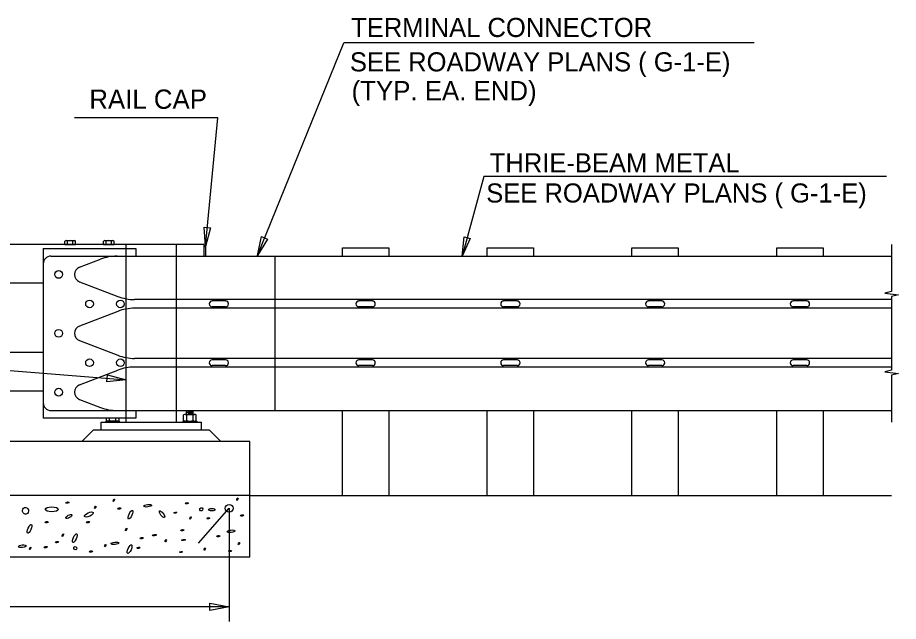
# Model space of a CAD drawing. Extents: x 0 to 45.3, y 0 to 31.4.
# Drawn here: x 13.86 to 23.37, y 13.57 to 20.09 of the extents above; entities that cross this region are included whole.
import ezdxf

# ---------------------------------------------------------------- set-up
doc = ezdxf.new("R2010")
doc.units = 0
for name, color, linetype in [('BRDG_ANNO_General-Notes', 7, 'Continuous'), ('BRDG_BASE_Hidden-Line', 7, 'Continuous'), ('BRDG_BASE_Obj-Line', 7, 'Continuous'), ('BRDG_BASE_Pattern', 7, 'Continuous'), ('BRDG_BASE_Rebar', 7, 'Continuous'), ('Default', 7, 'Continuous')]:
    doc.layers.add(name, color=color, linetype=linetype)

# ---------------------------------------------------------------- blocks, each defined once
blk = doc.blocks.new('TERM')
at = {"layer": 'Default'}
for p, q in [((-1.6, -0.267), (-1.6, 0.267)), ((-1.6, 0.267), (0, 0)), ((0, 0), (-1.6, -0.267))]:
    blk.add_line(p, q, dxfattribs=at)

msp = doc.modelspace()

# ---------------------------------------------------------------- linework, layer by layer
at = {"layer": 'BRDG_ANNO_General-Notes'}
for p, q in [((16.4516, 17.5248), (17.3838, 19.8198)), ((21.8149, 19.8198), (17.3838, 19.8198)), ((16.0251, 19.0123), (14.4785, 19.0123)), ((15.8907, 17.6226), (16.0251, 19.0123)), ((18.8974, 18.3786), (18.6603, 17.5184)), ((23.242, 18.3786), (18.8974, 18.3786)), ((15.8763, 17.8316), (15.9449, 17.825)), ((15.8907, 17.6226), (15.8763, 17.8316)), ((15.9449, 17.825), (15.8907, 17.6226)), ((16.4516, 17.5248), (16.4975, 17.7292)), ((16.5613, 17.7033), (16.4516, 17.5248)), ((16.4975, 17.7292), (16.5613, 17.7033)), ((18.6603, 17.5184), (18.682, 17.7268)), ((18.7484, 17.7085), (18.6603, 17.5184)), ((18.682, 17.7268), (18.7484, 17.7085)), ((6.9457, 16.8451), (15.0365, 16.1813)), ((14.8274, 16.1596), (14.8337, 16.2368)), ((15.0365, 16.1813), (14.8274, 16.1596)), ((14.8337, 16.2368), (15.0365, 16.1813)), ((16.1476, 14.7962), (16.1476, 13.5749)), ((16.1476, 13.7312), (11.1476, 13.7312))]:
    msp.add_line(p, q, dxfattribs=at)
at = {"layer": 'BRDG_BASE_Hidden-Line'}
for p, q in [((15.0365, 15.7684), (15.0365, 17.6434)), ((15.5782, 15.8518), (15.5782, 17.6434))]:
    msp.add_line(p, q, dxfattribs=at)
at = {"layer": 'BRDG_BASE_Obj-Line'}
for p, q in [((14.3738, 17.6434), (14.3738, 17.6818)), ((14.3881, 17.6864), (14.4324, 17.6864)), ((14.4031, 17.6434), (14.4031, 17.6818)), ((14.4324, 17.6864), (14.4767, 17.6864)), ((14.4617, 17.6434), (14.4617, 17.6818)), ((14.4909, 17.6434), (14.4909, 17.6818)), ((14.7905, 17.6434), (14.7905, 17.6818)), ((14.8047, 17.6864), (14.849, 17.6864)), ((14.8197, 17.6434), (14.8197, 17.6818)), ((14.849, 17.6864), (14.8933, 17.6864)), ((14.8783, 17.6434), (14.8783, 17.6818)), ((14.9076, 17.6434), (14.9076, 17.6818)), ((15.8751, 17.6434), (3.8074, 17.6434)), ((14.1407, 17.6018), (14.1407, 15.7684)), ((14.1407, 17.6018), (15.1407, 17.6018)), ((14.3738, 17.6434), (14.4324, 17.6434)), ((14.4324, 17.6434), (14.4909, 17.6434)), ((14.7905, 17.6434), (14.849, 17.6434)), ((14.849, 17.6434), (14.9076, 17.6434)), ((15.1407, 17.6018), (15.1407, 17.5184)), ((15.8751, 17.6434), (15.8751, 17.5184)), ((15.8751, 17.6226), (15.8907, 17.6226)), ((15.8907, 17.6226), (15.8907, 17.5184)), ((17.3699, 17.607), (17.8699, 17.607)), ((17.3699, 17.5184), (17.3699, 17.607)), ((17.8699, 17.607), (17.8699, 17.5184)), ((18.9324, 17.607), (19.4324, 17.607)), ((18.9324, 17.5184), (18.9324, 17.607)), ((19.4324, 17.607), (19.4324, 17.5184)), ((20.4949, 17.607), (20.9949, 17.607)), ((20.4949, 17.5184), (20.4949, 17.607)), ((20.9949, 17.607), (20.9949, 17.5184)), ((22.0574, 17.607), (22.5574, 17.607)), ((22.0574, 17.5184), (22.0574, 17.607)), ((22.5574, 17.607), (22.5574, 17.5184)), ((14.224, 17.5184), (16.6407, 17.5184)), ((16.6407, 17.5184), (23.2959, 17.5184)), ((16.6407, 17.5184), (16.6407, 15.8518)), ((14.1407, 17.4351), (14.1407, 15.9351)), ((14.5329, 17.3982), (14.7573, 17.4849)), ((14.1407, 17.2268), (3.8074, 17.2268)), ((14.5329, 17.2428), (14.9461, 17.0832)), ((16.6407, 17.0497), (15.1262, 17.0497)), ((23.2959, 17.0497), (16.6407, 17.0497)), ((14.9462, 16.9224), (14.5329, 16.7628)), ((16.6407, 16.9559), (15.1262, 16.9559)), ((23.2959, 16.9559), (16.6407, 16.9559)), ((14.5329, 16.6074), (14.9461, 16.4478)), ((14.1407, 16.4768), (3.8074, 16.4768)), ((16.6407, 16.4143), (15.1262, 16.4143)), ((23.2959, 16.4143), (16.6407, 16.4143)), ((14.5329, 16.1274), (14.9461, 16.287)), ((16.6407, 16.3205), (15.1262, 16.3205)), ((23.2959, 16.3205), (16.6407, 16.3205)), ((14.1407, 16.0601), (3.8074, 16.0601)), ((14.5329, 15.972), (14.7573, 15.8853)), ((14.224, 15.8518), (16.6407, 15.8518)), ((15.1407, 15.8518), (15.1407, 15.7684)), ((15.5782, 15.7268), (15.5782, 15.8518)), ((15.6557, 15.7426), (15.6557, 15.8047)), ((15.6732, 15.8101), (15.724, 15.8101)), ((15.6876, 15.8101), (15.6876, 15.8518)), ((15.6876, 15.8344), (15.7605, 15.8344)), ((15.6898, 15.7426), (15.6898, 15.8047)), ((15.6997, 15.8466), (15.7484, 15.8466)), ((15.6997, 15.8223), (15.7484, 15.8223)), ((15.724, 15.8101), (15.7749, 15.8101)), ((15.7582, 15.7426), (15.7582, 15.8047)), ((15.7605, 15.8101), (15.7605, 15.8518)), ((15.7924, 15.7426), (15.7924, 15.8047)), ((16.6407, 15.8518), (23.2959, 15.8518)), ((17.3699, 14.9351), (17.3699, 15.8518)), ((17.8699, 15.8518), (17.8699, 14.9351)), ((18.9324, 14.9351), (18.9324, 15.8518)), ((19.4324, 15.8518), (19.4324, 14.9351)), ((20.4949, 14.9351), (20.4949, 15.8518)), ((20.9949, 15.8518), (20.9949, 14.9351)), ((22.0574, 14.9351), (22.0574, 15.8518)), ((22.5574, 15.8518), (22.5574, 14.9351)), ((15.1407, 15.7684), (14.1407, 15.7684)), ((14.7657, 15.7268), (15.849, 15.7268)), ((14.7657, 15.6434), (14.7657, 15.7268)), ((14.8224, 15.7426), (14.8224, 15.7684)), ((14.8907, 15.7372), (14.8399, 15.7372)), ((14.8565, 15.7426), (14.8565, 15.7684)), ((14.9415, 15.7372), (14.8907, 15.7372)), ((14.9249, 15.7426), (14.9249, 15.7684)), ((14.959, 15.7426), (14.959, 15.7684)), ((15.0365, 15.7268), (15.0365, 15.7684)), ((15.6732, 15.7372), (15.724, 15.7372)), ((15.724, 15.7372), (15.7749, 15.7372)), ((15.849, 15.6434), (15.849, 15.7268)), ((14.5573, 15.5184), (14.6823, 15.6434)), ((14.6823, 15.6434), (15.9324, 15.6434)), ((16.0574, 15.5184), (15.9324, 15.6434)), ((16.3699, 15.5184), (2.6751, 15.5184)), ((16.3699, 14.9351), (16.3699, 15.5184)), ((16.3699, 14.9351), (2.6751, 14.9351)), ((16.3699, 14.9351), (23.2959, 14.9351)), ((16.3699, 14.2684), (16.3699, 14.9351)), ((16.3699, 14.2684), (2.6751, 14.2684))]:
    msp.add_line(p, q, dxfattribs=at)
msp.add_lwpolyline([(23.2959, 17.6447), (23.2959, 17.1372), (23.2221, 17.1188), (23.3698, 17.1003), (23.2959, 17.0819), (23.2959, 16.6851), (23.2959, 16.2883), (23.2221, 16.2699), (23.3698, 16.2514), (23.2959, 16.233), (23.2959, 15.7255)], dxfattribs=at)
for points in [[(14.9636, 15.7268), (14.9636, 15.7372), (14.8178, 15.7372), (14.8178, 15.7268)], [(15.6511, 15.7268), (15.6511, 15.7372), (15.7969, 15.7372), (15.7969, 15.7268)]]:
    msp.add_lwpolyline(points, close=True, dxfattribs=at)
for centre, radius, start, end in [((14.3884, 17.661), 0.0254, 54.7697, 125.2303), ((14.4324, 17.5918), 0.0946, 71.96845, 108.03155), ((14.4763, 17.661), 0.0254, 54.7697, 125.2303), ((14.8051, 17.661), 0.0254, 54.7697, 125.2303), ((14.849, 17.5918), 0.0946, 71.96845, 108.03155), ((14.893, 17.661), 0.0254, 54.7697, 125.2303), ((14.224, 17.4351), 0.0833, 90, 180), ((14.9374, 17.0184), 0.5, 90, 111.10753), ((14.563, 17.3205), 0.0833, 111.11599, 248.88034), ((15.1262, 17.5497), 0.5, 248.89319, 270), ((15.1262, 16.4559), 0.5, 90, 111.09879), ((14.563, 16.6851), 0.0833, 111.11998, 248.88366), ((15.1262, 16.9143), 0.5, 248.88039, 270), ((15.1262, 15.8205), 0.5, 90, 111.10681), ((14.563, 16.0497), 0.0833, 111.11966, 248.88401), ((14.224, 15.9351), 0.0833, 180, 270), ((14.9374, 16.3518), 0.5, 248.89247, 270), ((15.6728, 15.7805), 0.0296, 54.7697, 125.2303), ((15.724, 15.6997), 0.1104, 71.96845, 108.03155), ((15.7753, 15.7805), 0.0296, 54.7697, 125.2303), ((14.8394, 15.7668), 0.0296, 234.7697, 305.2303), ((14.8907, 15.8476), 0.1104, 251.96845, 288.03155), ((14.942, 15.7668), 0.0296, 234.7697, 305.2303), ((15.6728, 15.7668), 0.0296, 234.7697, 305.2303), ((15.724, 15.8476), 0.1104, 251.96845, 288.03155), ((15.7753, 15.7668), 0.0296, 234.7697, 305.2303)]:
    msp.add_arc(centre, radius, start, end, dxfattribs=at)
at = {"layer": 'BRDG_BASE_Pattern'}
for centre, major_axis, ratio in [((14.4029, 14.8571), (-0.0164, -0.0024), 0.420578), ((14.9035, 14.8823), (0.0059, 0.0129), 0.353486), ((15.2681, 14.8241), (-0.0423, -0.0047), 0.315594), ((15.6923, 14.8501), (-0.0164, -0.0024), 0.420578), ((16.2362, 14.8944), (0.0059, 0.0129), 0.353486), ((13.9488, 14.7694), (-0.0094, 0.0352), 0.905037), ((14.233, 14.7847), (0.0705, 0), 0.363671), ((14.4181, 14.708), (0.0329, 0.0188), 0.385178), ((14.6342, 14.7291), (0.047, 0.0211), 0.389672), ((14.7023, 14.8066), (0.0059, 0.0129), 0.353486), ((14.9618, 14.7937), (-0.0164, -0.0024), 0.420578), ((15.0828, 14.7268), (0.0211, 0.047), 0.317581), ((15.4229, 14.7317), (0.0258, -0.0352), 0.360274), ((15.5681, 14.7485), (-0.0164, -0.0024), 0.420578), ((15.8467, 14.785), (-0.0047, 0.0176), 0.905037), ((15.9594, 14.7816), (0.0352, 0), 0.363671), ((14.1783, 14.6453), (-0.0164, -0.0024), 0.420578), ((14.6233, 14.6463), (-0.0164, -0.0024), 0.420578), ((15.731, 14.6915), (0.0059, 0.0129), 0.353486), ((15.9225, 14.688), (-0.0164, -0.0024), 0.420578), ((16.286, 14.7192), (-0.0164, -0.0024), 0.420578), ((13.9934, 14.5744), (0.0211, 0.047), 0.317581), ((15.0361, 14.5669), (0.0059, 0.0129), 0.353486), ((15.6435, 14.559), (-0.0164, -0.0024), 0.420578), ((16.1684, 14.5483), (-0.0423, -0.0047), 0.315594), ((14.3523, 14.506), (0.0059, 0.0129), 0.353486), ((14.4815, 14.4731), (0.0211, 0.047), 0.317581), ((15.2025, 14.4742), (-0.0164, -0.0024), 0.420578), ((15.3408, 14.5055), (-0.0211, -0.0024), 0.315594), ((15.4632, 14.4461), (0.0059, 0.0129), 0.353486), ((15.6535, 14.4536), (-0.0211, -0.0024), 0.315594), ((16.0314, 14.494), (-0.0164, -0.0024), 0.420578), ((13.9159, 14.3865), (-0.0423, -0.0047), 0.315594), ((14.0005, 14.3631), (0.0059, 0.0129), 0.353486), ((14.1673, 14.3761), (-0.0164, -0.0024), 0.420578), ((14.2885, 14.4311), (-0.0164, -0.0024), 0.420578), ((14.4863, 14.3656), (-0.0047, 0.0176), 0.905037), ((14.8103, 14.3932), (0.0059, 0.0129), 0.353486), ((14.9147, 14.4179), (-0.0423, -0.0047), 0.315594), ((15.0734, 14.3557), (0.0211, 0.047), 0.317581), ((15.1685, 14.37), (-0.0164, -0.0024), 0.420578), ((15.8837, 14.3557), (0.0059, 0.0129), 0.353486), ((16.2532, 14.4146), (0.0059, 0.0129), 0.353486), ((14.6565, 14.3286), (-0.0164, -0.0024), 0.420578), ((15.6289, 14.3239), (-0.0164, -0.0024), 0.420578), ((16.1552, 14.3344), (-0.0164, -0.0024), 0.420578)]:
    msp.add_ellipse(centre, major_axis=major_axis, ratio=ratio, dxfattribs=at)
at = {"layer": 'BRDG_BASE_Rebar'}
for p, q in [((16.1094, 17.0341), (15.9636, 17.0341)), ((17.6928, 17.0341), (17.5469, 17.0341)), ((19.2553, 17.0341), (19.1094, 17.0341)), ((20.8178, 17.0341), (20.6719, 17.0341)), ((22.3803, 17.0341), (22.2344, 17.0341)), ((16.1094, 16.9716), (15.9636, 16.9716)), ((17.6928, 16.9716), (17.5469, 16.9716)), ((19.2553, 16.9716), (19.1094, 16.9716)), ((20.8178, 16.9716), (20.6719, 16.9716)), ((22.3803, 16.9716), (22.2344, 16.9716)), ((16.1094, 16.3986), (15.9636, 16.3986)), ((17.6928, 16.3986), (17.5469, 16.3986)), ((19.2553, 16.3986), (19.1094, 16.3986)), ((20.8178, 16.3986), (20.6719, 16.3986)), ((22.3803, 16.3986), (22.2344, 16.3986)), ((16.1094, 16.3361), (15.9636, 16.3361)), ((17.6928, 16.3361), (17.5469, 16.3361)), ((19.2553, 16.3361), (19.1094, 16.3361)), ((20.8178, 16.3361), (20.6719, 16.3361)), ((22.3803, 16.3361), (22.2344, 16.3361)), ((15.8169, 14.4212), (16.1476, 14.7962))]:
    msp.add_line(p, q, dxfattribs=at)
for centre in [(14.3074, 17.3205), (14.6407, 17.0028), (14.974, 17.0028), (14.3074, 16.6851), (14.6407, 16.3674), (14.974, 16.3674), (14.3074, 16.0497), (16.1476, 14.7962)]:
    msp.add_circle(centre, 0.0417, dxfattribs=at)
for centre, start, end in [((15.9636, 17.0028), 90, 270), ((16.1094, 17.0028), 270, 90), ((17.5469, 17.0028), 90, 270), ((17.6928, 17.0028), 270, 90), ((19.1094, 17.0028), 90, 270), ((19.2553, 17.0028), 270, 90), ((20.6719, 17.0028), 90, 270), ((20.8178, 17.0028), 270, 90), ((22.2344, 17.0028), 90, 270), ((22.3803, 17.0028), 270, 90), ((15.9636, 16.3674), 90, 270), ((16.1094, 16.3674), 270, 90), ((17.5469, 16.3674), 90, 270), ((17.6928, 16.3674), 270, 90), ((19.1094, 16.3674), 90, 270), ((19.2553, 16.3674), 270, 90), ((20.6719, 16.3674), 90, 270), ((20.8178, 16.3674), 270, 90), ((22.2344, 16.3674), 90, 270), ((22.3803, 16.3674), 270, 90)]:
    msp.add_arc(centre, 0.0312, start, end, dxfattribs=at)

# ---------------------------------------------------------------- block references
at = {"layer": 'BRDG_ANNO_General-Notes', "xscale": 0.13020833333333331, "yscale": 0.146484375}
msp.add_blockref('TERM', (16.1476, 13.7312), dxfattribs=at)

# ---------------------------------------------------------------- texts
at = {"layer": 'BRDG_ANNO_General-Notes'}
for s, height, p in [('TERMINAL CONNECTOR', 0.20625, (17.4641, 19.8844)), ('SEE ROADWAY PLANS ( G-1-E)', 0.20625, (17.4505, 19.513)), ('(TYP. EA. END)', 0.208333, (17.4689, 19.2007)), ('RAIL CAP', 0.20833, (14.6383, 19.1089)), ('THRIE-BEAM METAL ', 0.20625, (18.9597, 18.4225)), ('SEE ROADWAY PLANS ( G-1-E)', 0.20625, (18.9215, 18.0972))]:
    msp.add_text(s, height=height, dxfattribs=at).set_placement(p)

doc.saveas('drawing.dxf')
